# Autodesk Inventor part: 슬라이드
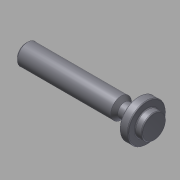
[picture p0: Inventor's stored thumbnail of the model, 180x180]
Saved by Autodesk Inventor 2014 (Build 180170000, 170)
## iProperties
Company: 한국ATC센터
Created: 2015-12
Part Number: 슬라이드
Document SubType Name: Modeling
Designer: mdu
Density: 7.86 g/cm^3
Mass: 72.8967 g
Surface Area: 36.3054 cm^2
Volume: 9.27439 cm^3
Material: 강철, 연강
Appearance: 강철
Author: mdu
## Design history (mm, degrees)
sketch "스케치1"
  geometry: L1 (-35, 0)-(35, 0); L2 (35, 0)-(35, 11); L3 (35, 11)-(30, 11); L4 (30, 11)-(30, 4); L5 (30, 4)-(22, 4); L6 (22, 4)-(20, 6); L7 (20, 6)-(-35, 6); L8 (-35, 6)-(-35, 0); 1 further point
  constraints: 16 end point, 4 parallel, 2 midpoint, 2 perpendicular, 1 horizontal
  dimensions: "d0" = 70 distance of L1.start L1.end; "d1" = 12 diameter of L7 L1; "d2" = 22 diameter of L3 L1; "d3" = 5 distance of L2.end L3.end; "d4" = 8 diameter of L5 L1; "d5" = 135 deg angle of L6 L5; "d6" = 15 distance from line of L2 L6.end
revolve "회전1" sketch "스케치1" stored, may be unused: angle "d7" = 90 deg
chamfer "모따기1" distance "d8" = 1; stored, may be unused: second distance "d9" = 2, angle "d10" = 45 deg
fillet "모깎기1" dims "d11" = 0.5
sketch "스케치5"
  geometry: C1 r 7 at (0, 0); 1 further point
  constraints: 1 centre point, 1 coincident
  dimensions: "d23" = 14 diameter of C1
extrude "돌출2" join sketch "스케치5" distance "d24" = 4; taper "d25" = 0 deg
fillet "모깎기3" dims "d26" = 0.5
node "솔리드1"
